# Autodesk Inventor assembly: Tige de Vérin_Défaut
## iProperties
Shininess: 64.0
Length Units: 11269
Angle Units: 11279
Time Units: 11290
Mass Units: 11283
Length Display Precision: 3
Angle Display Precision: 2
Compacted: True
Created: 2006-11
Part Number: Tige de Vérin_Défaut
Document SubType Name: Assembly
Designer: profs_sti
Density: 0.0
Volumn: 0.0
Area: 0.0
PropertySet Name: Model Information
Control State: 0
Master: False
Checked Out: False
Author: profs_sti
